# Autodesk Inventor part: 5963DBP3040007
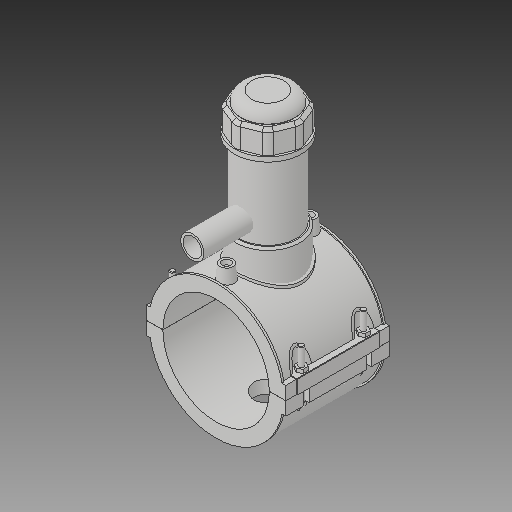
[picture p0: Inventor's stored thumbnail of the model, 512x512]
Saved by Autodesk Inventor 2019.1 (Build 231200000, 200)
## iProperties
Created: 2017-07
Part Number: 5963DBP3040007
Material: Generic
Description: PLASSON TAPPING SADDLE 4''DIPS x 3/4''IPS
Document SubType Name: Modeling
Designer: KIM
Density: 1 g/cm^3
Appearance: Default
Author: KIM
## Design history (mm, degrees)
derived "5963DBP_5963BUP.ipt"
feature "Solid1::5963DBP_5963BUP.ipt"
feature "Solid2::5963DBP_5963BUP.ipt"
feature "Solid3::5963DBP_5963BUP.ipt"
tag "TaggingFeature1"
body "Solid1"
body "Solid2"
body "Solid3"
other parameters: "d0" = 121.3, "d2" = 159.004, "d3" = 30.325, "d4" = 118.11, "d5" = 0, "d6" = 0.1, "d8" = 0, "d19" = 6, "d20" = 6, "d21" = 70.866, "d23" = 0, "d24" = 35.433, "d26" = 0, "d27" = 3, "d28" = 3, "d29" = 3, "d30" = 40.43333, "d31" = 6, "d32" = 0, "d33" = 0, "d34" = 0.6, "d40" = 78.21424, "d41" = 76.419, "d43" = 0, "d45" = 0, "d47" = 146.072, "d70" = 15, "d72" = 0, "d73" = 6, "d75" = 5, "d76" = 0, "d77" = 6.065, "d78" = 90.65, "d79" = 15, "d80" = 47.244, "d82" = 5 deg, "d84" = 4, "d85" = 14, "d86" = 0, "d87" = 3, "d88" = 0, "d89" = 1, "d90" = 1, "d91" = 94.488, "d92" = 0, "d93" = 0.5, "d94" = 63.84211, "d96" = 153.42024, "d97" = 2.3622, "d98" = 0, "d120" = 140 deg, "d121" = 24.228, "d122" = 20 deg, "d123" = 300.824, "d124" = 90.2472, "d126" = 0, "d143" = 124.939, "d145" = 22.39385, "d149" = 1.8195, "d150" = 24.63323, "d153" = 118.11, "d154" = 0, "d156" = 75.206, "d157" = 160 deg, "d159" = 5.8224, "d161" = 1.8195, "d162" = 70.866, "d163" = 0, "d164" = 60.65, "d167" = 12.13, "d168" = 73.37171, "d170" = 3.4335, "d172" = 0, "d173" = 1, "d175" = 60.65, "d176" = 20 deg, "d177" = 8.491, "d178" = 29.112, "d180" = 0, "d183" = 11.6448, "d184" = 6.7928, "d185" = 38.38575, "d186" = 38.38575, "d187" = 75.206, "d188" = 8.7336, "d189" = 8.491, "d190" = 0, "d191" = 112.809, "d193" = 7.3248, "d194" = 4.13385, "d195" = 90 deg, "d197" = 0, "d199" = 0, "d200" = 14.556, "d202" = 0, "d203" = 177.038, "d204" = 72.59805, "d205" = 53.4933, "d206" = 64.95615, "d207" = 132.7785, "d208" = 138.08964, "d209" = 164.64534, "d210" = 65.72034, "d211" = 76.419, "d212" = 61.1352, "d213" = 46.5516, "d216" = 0, "d217" = 12.13, "d218" = 12.13, "d219" = 2.426, "d222" = 121.3, "d224" = 0, "d225" = 65.024, "d226" = 26.6, "d227" = 21.28, "d228" = 86.106, "d230" = 3.639, "d_" = 121.3, "B_" = 159.004, "L_" = 118.11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
